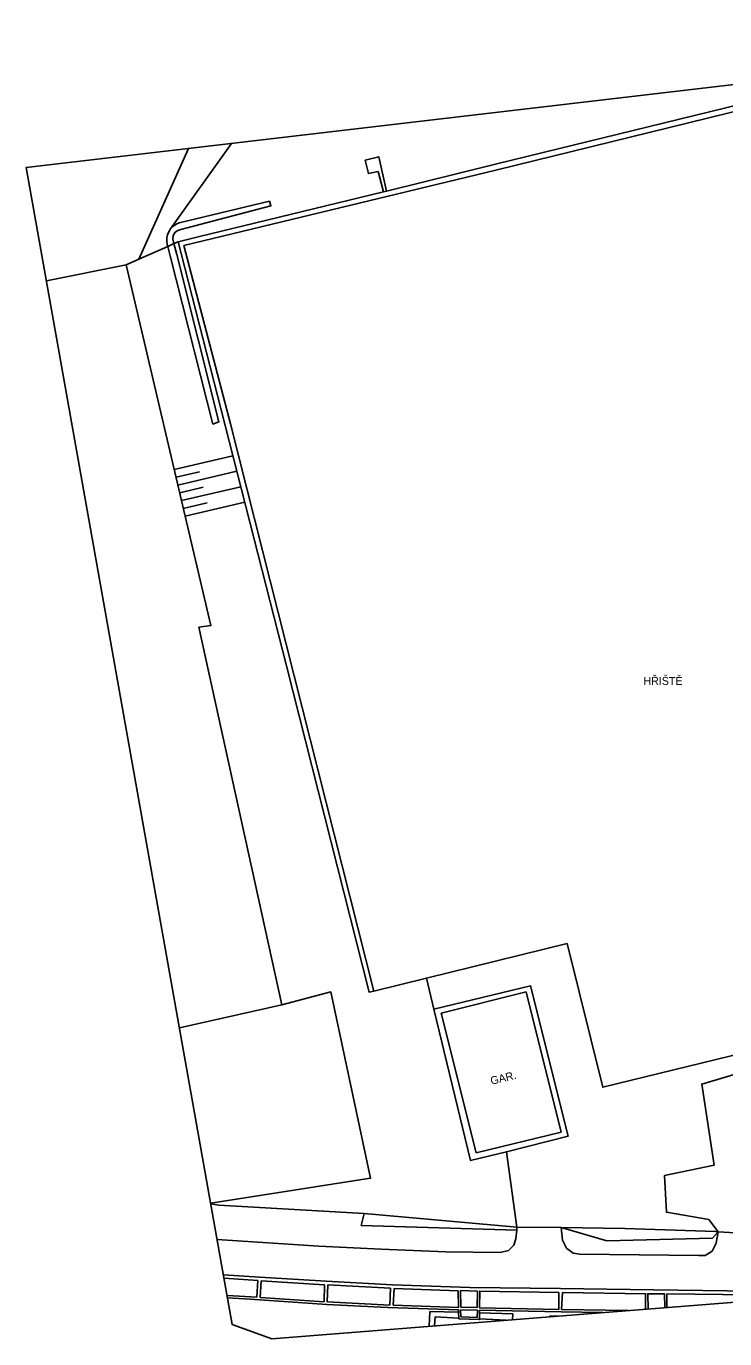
# Model space of a CAD drawing. Extents: x -597791 to -597535, y -1159670 to -1159547.
# Drawn here: x -597791.5 to -597726, y -1159669.5 to -1159546.5 of the extents above; entities that cross this region are included whole.
import ezdxf

# ---------------------------------------------------------------- set-up
doc = ezdxf.new("R2010")
doc.units = 0
doc.layers.add('MAPA', color=7, linetype='Continuous')
doc.layers.add('Žádosti', color=7, linetype='Continuous')

msp = doc.modelspace()

# ---------------------------------------------------------------- linework, layer by layer
at = {"layer": 'MAPA'}
for p, q in [((-597780.91, -1159568.34), (-597776.26, -1159557.95)), ((-597772.22, -1159557.48), (-597777.93, -1159565.5)), ((-597789.56, -1159570.38), (-597782.1, -1159568.86)), ((-597767.5, -1159638.24), (-597777.1, -1159640.39)), ((-597773.42, -1159657), (-597774.16, -1159656.89)), ((-597764.05, -1159660.85), (-597773.57, -1159660.22)), ((-597772.98, -1159663.54), (-597769.61, -1159663.77)), ((-597772.92, -1159663.87), (-597769.77, -1159664.08)), ((-597769.85, -1159665.65), (-597772.63, -1159665.48)), ((-597731.42, -1159666.61), (-597731.44, -1159665.33)), ((-597770.49, -1159665.84), (-597772.59, -1159665.71)), ((-597735.03, -1159666.89), (-597741.29, -1159666.79)), ((-597753.71, -1159668.37), (-597753.65, -1159666.98)), ((-597753.19, -1159668.33), (-597753.15, -1159667.49)), ((-597748.98, -1159667.68), (-597746.49, -1159667.8)), ((-597745.86, -1159667.19), (-597745.88, -1159667.75)), ((-597741.66, -1159667.42), (-597742.41, -1159667.42)), ((-597737.44, -1159667.08), (-597741.34, -1159667.02))]:
    msp.add_line(p, q, dxfattribs=at)
for points in [[(-597758.88, -1159636.94), (-597772.32, -1159583.78), (-597776.69, -1159567.07), (-597747.44, -1159559.98), (-597720.38, -1159553.34), (-597713.57, -1159558.21), (-597713.41, -1159558.33), (-597705.98, -1159569.62)], [(-597757.7, -1159561.95), (-597747.37, -1159559.39), (-597720.29, -1159552.78), (-597713.03, -1159557.95), (-597705.52, -1159569.32)], [(-597757.97, -1159562.03), (-597758.49, -1159560.12), (-597759.39, -1159560.32), (-597759.7, -1159559.06), (-597758.42, -1159558.74), (-597757.7, -1159561.95)], [(-597777.23, -1159566.71), (-597775.35, -1159566.25), (-597757.97, -1159562.03)], [(-597757.97, -1159562.03), (-597757.7, -1159561.95)], [(-597778.24, -1159566.97), (-597778.3, -1159566.62), (-597778.28, -1159566.35), (-597778.23, -1159566.06), (-597778.11, -1159565.77), (-597777.93, -1159565.5), (-597777.71, -1159565.27), (-597777.41, -1159565.06), (-597777.12, -1159564.94), (-597768.68, -1159562.89)], [(-597768.68, -1159562.89), (-597768.53, -1159563.33), (-597776.96, -1159565.55), (-597777.24, -1159565.64), (-597777.5, -1159565.82), (-597777.68, -1159566.11), (-597777.72, -1159566.47)], [(-597782.1, -1159568.86), (-597780.91, -1159568.34), (-597778.2, -1159567.14)], [(-597778.2, -1159567.14), (-597778.24, -1159566.97)], [(-597777.62, -1159566.88), (-597777.36, -1159567.9), (-597773.4, -1159583.59), (-597773.96, -1159583.79), (-597777.97, -1159568.02), (-597778.2, -1159567.14)], [(-597778.2, -1159567.14), (-597777.62, -1159566.88)], [(-597777.72, -1159566.47), (-597777.62, -1159566.88)], [(-597777.62, -1159566.88), (-597777.23, -1159566.71)], [(-597758.88, -1159636.94), (-597759.33, -1159637.04), (-597767.07, -1159606.46), (-597773.2, -1159582.47), (-597776.95, -1159567.81), (-597777.23, -1159566.71)], [(-597774.17, -1159656.84), (-597759.19, -1159654.49), (-597762.92, -1159637.02), (-597767.5, -1159638.24), (-597775.28, -1159602.84), (-597774.16, -1159602.68), (-597782.1, -1159568.86)], [(-597777.59, -1159588.05), (-597772.1, -1159586.76)], [(-597777.42, -1159588.78), (-597775.22, -1159588.27)], [(-597777.25, -1159589.51), (-597771.73, -1159588.22)], [(-597777.08, -1159590.24), (-597774.87, -1159589.72)], [(-597776.91, -1159590.97), (-597771.36, -1159589.67)], [(-597776.74, -1159591.7), (-597774.51, -1159591.18)], [(-597776.57, -1159592.43), (-597770.99, -1159591.12)], [(-597690.2, -1159634.37), (-597702, -1159637.24), (-597702.58, -1159636.66), (-597711.7, -1159638.91), (-597711.53, -1159639.64), (-597724.12, -1159642.71), (-597737.44, -1159645.96), (-597740.78, -1159632.5), (-597753.96, -1159635.73), (-597758.88, -1159636.94)], [(-597753.26, -1159638.64), (-597753.96, -1159635.73)], [(-597753.26, -1159638.64), (-597744.21, -1159636.45), (-597740.69, -1159650.56), (-597746.46, -1159652), (-597749.82, -1159652.84), (-597753.26, -1159638.64)], [(-597744.62, -1159637.02), (-597752.57, -1159639)], [(-597744.62, -1159637.02), (-597741.34, -1159650.16)], [(-597752.57, -1159639), (-597749.3, -1159652.12)], [(-597726.62, -1159659.5), (-597727.5, -1159658.36), (-597731.47, -1159657.68), (-597731.64, -1159654.22), (-597727, -1159653.26), (-597728.16, -1159645.66), (-597723.64, -1159644.34)], [(-597741.34, -1159650.16), (-597749.3, -1159652.12)], [(-597745.48, -1159659.08), (-597746.46, -1159652)], [(-597745.48, -1159659.08), (-597759.8, -1159657.79), (-597773.42, -1159657)], [(-597759.8, -1159657.79), (-597760.06, -1159658.93)], [(-597745.5, -1159659.36), (-597760.06, -1159658.93)], [(-597745.5, -1159659.36), (-597745.58, -1159660.16)], [(-597745.5, -1159659.36), (-597745.48, -1159659.08)], [(-597745.48, -1159659.08), (-597741.33, -1159659.11)], [(-597741.33, -1159659.11), (-597741.2, -1159660.29)], [(-597726.62, -1159659.5), (-597727.15, -1159660.1), (-597737.05, -1159660.35), (-597741.33, -1159659.11)], [(-597726.62, -1159659.5), (-597726.86, -1159659.49), (-597735.37, -1159659.21), (-597741.33, -1159659.11)], [(-597745.58, -1159660.16), (-597745.77, -1159660.77)], [(-597741.2, -1159660.29), (-597740.84, -1159661.04)], [(-597726.79, -1159660.57), (-597727.18, -1159661.32), (-597727.83, -1159661.72)], [(-597726.79, -1159660.57), (-597726.62, -1159659.5)], [(-597726.62, -1159659.5), (-597722.35, -1159659.75)], [(-597747.06, -1159661.46), (-597752.15, -1159661.38), (-597758.21, -1159661.14), (-597764.05, -1159660.85)], [(-597745.77, -1159660.77), (-597746.28, -1159661.25), (-597747.06, -1159661.46)], [(-597739.59, -1159661.61), (-597740.22, -1159661.51), (-597740.84, -1159661.04)], [(-597739.59, -1159661.61), (-597728.46, -1159661.74), (-597727.83, -1159661.72)], [(-597769.77, -1159664.08), (-597769.85, -1159665.65)], [(-597741.39, -1159664.84), (-597749.88, -1159664.72), (-597757.14, -1159664.47), (-597763.35, -1159664.14), (-597769.61, -1159663.77)], [(-597769.53, -1159665.68), (-597769.45, -1159664.1)], [(-597769.45, -1159664.1), (-597763.5, -1159664.47)], [(-597763.5, -1159664.47), (-597763.53, -1159666.07)], [(-597763.19, -1159664.49), (-597763.27, -1159666.07)], [(-597757.31, -1159664.79), (-597763.19, -1159664.49)], [(-597757.39, -1159666.39), (-597757.31, -1159664.79)], [(-597750.98, -1159665.03), (-597756.98, -1159664.81), (-597757.08, -1159666.39)], [(-597750.98, -1159665.03), (-597750.94, -1159666.6), (-597757.08, -1159666.39)], [(-597750.72, -1159666.59), (-597750.76, -1159665.02)], [(-597750.76, -1159665.02), (-597749.18, -1159665.06)], [(-597749.18, -1159665.06), (-597749.2, -1159666.61)], [(-597741.56, -1159666.78), (-597748.98, -1159666.64), (-597748.96, -1159665.06), (-597741.54, -1159665.19)], [(-597741.54, -1159665.19), (-597741.56, -1159666.78)], [(-597723.47, -1159665.08), (-597732.68, -1159664.96), (-597741.39, -1159664.84)], [(-597741.29, -1159666.79), (-597741.22, -1159665.19)], [(-597741.22, -1159665.19), (-597733.42, -1159665.31), (-597733.42, -1159666.77)], [(-597733.19, -1159666.75), (-597733.22, -1159665.31), (-597731.65, -1159665.32), (-597731.63, -1159666.62)], [(-597723.6, -1159665.43), (-597731.44, -1159665.33)], [(-597763.3, -1159666.32), (-597770.49, -1159665.84)], [(-597763.53, -1159666.07), (-597769.53, -1159665.68)], [(-597763.3, -1159666.32), (-597757.56, -1159666.61)], [(-597763.27, -1159666.07), (-597757.39, -1159666.39)], [(-597757.56, -1159666.61), (-597750.95, -1159666.83)], [(-597748.97, -1159666.87), (-597748.97, -1159667.11), (-597748.98, -1159667.68), (-597748.98, -1159667.74), (-597750.91, -1159667.68), (-597750.91, -1159667.59), (-597750.94, -1159667.05), (-597750.95, -1159666.83)], [(-597749.18, -1159666.86), (-597749.19, -1159667.53), (-597750.72, -1159667.48), (-597750.75, -1159666.81)], [(-597749.18, -1159666.86), (-597750.75, -1159666.81)], [(-597749.2, -1159666.61), (-597750.72, -1159666.59)], [(-597753.65, -1159666.98), (-597750.94, -1159667.05)], [(-597750.91, -1159667.59), (-597753.15, -1159667.49)], [(-597741.34, -1159667.02), (-597748.97, -1159666.87)], [(-597748.97, -1159667.11), (-597745.86, -1159667.19)]]:
    msp.add_lwpolyline(points, dxfattribs=at)
at = {"layer": 'Žádosti'}
msp.add_lwpolyline([(-597654.67, -1159660.54), (-597678.48, -1159546.5), (-597791.46, -1159559.73), (-597772.15, -1159668.21), (-597768.44, -1159669.54)], close=True, dxfattribs=at)

# ---------------------------------------------------------------- texts
at = {"layer": 'MAPA'}
msp.add_text('HŘIŠTĚ', height=0.75, dxfattribs=at).set_placement((-597733.63, -1159608.25))
msp.add_text('GAR.', height=0.75, rotation=13.8328, dxfattribs=at).set_placement((-597747.86, -1159645.74))

doc.saveas('drawing.dxf')
